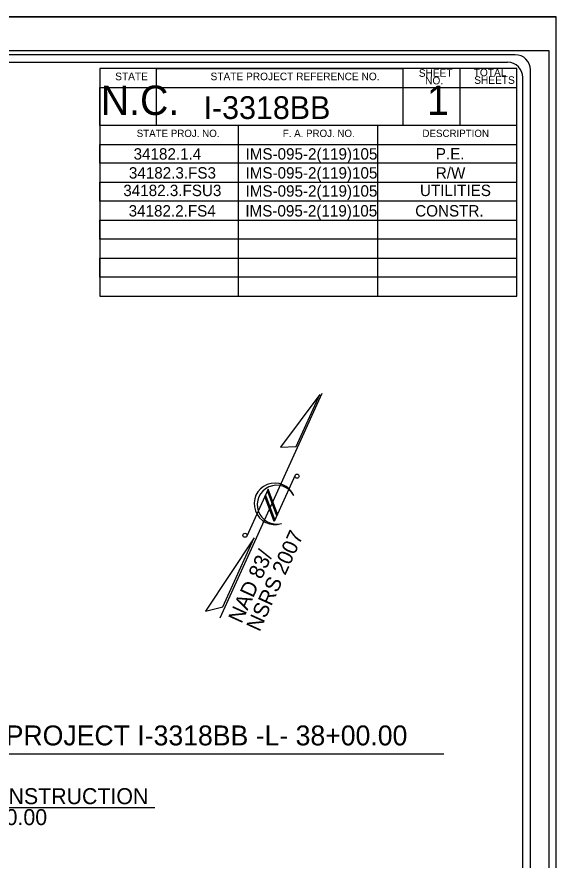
# Model space of a CAD drawing. Extents: x 2241278 to 2254132, y 649924 to 670434.
# Drawn here: x 2251201 to 2252979, y 663621 to 666399 of the extents above; entities that cross this region are included whole.
import ezdxf

# ---------------------------------------------------------------- set-up
doc = ezdxf.new("R2010")
doc.units = 0
for name, color, linetype in [('Prop RDY Alternate Text Yellow', 7, 'Continuous'), ('Sheet Cutting Line CELL', 7, 'Continuous'), ('Sheet Data Field CELL', 7, 'Continuous'), ('Sheet North Arrow CELL', 7, 'Continuous'), ('Sheet Plot Border Inside CELL', 7, 'Continuous'), ('Sheet Plot Border Outside CELL', 7, 'Continuous'), ('Sheet Title CELL', 7, 'Continuous')]:
    doc.layers.add(name, color=color, linetype=linetype)

msp = doc.modelspace()

# ---------------------------------------------------------------- linework, layer by layer
at = {"layer": 'Prop RDY Alternate Text Yellow'}
for p, q in [((2250713.3, 663970.9), (2252608.4, 663970.9)), ((2250873, 663794.9), (2251656.1, 663794.9))]:
    msp.add_line(p, q, dxfattribs=at)
at = {"layer": 'Sheet Cutting Line CELL'}
msp.add_line((2244558.8, 666399.1), (2252978.8, 666399.1), dxfattribs=at)
at = {"layer": 'Sheet North Arrow CELL'}
for p, q in [((2251870.9, 664419.5), (2252207.8, 665158.9)), ((2252118.4, 664888.9), (2252049.3, 664737.1)), ((2252029.3, 664843.1), (2251959, 664688.8)), ((2252060.1, 664760.8), (2252029.3, 664843.1)), ((2252049.3, 664737.1), (2252018.5, 664819.4)), ((2252026.8, 664837.5), (2252020.4, 664823.6)), ((2252051.2, 664741.3), (2252020.4, 664823.6)), ((2252020.4, 664823.6), (2252051.2, 664741.3)), ((2252057.5, 664755.2), (2252026.8, 664837.5)), ((2252113.6, 664822.8), (2252114.1, 664821.9)), ((2252051.2, 664741.3), (2252057.5, 664755.2))]:
    msp.add_line(p, q, dxfattribs=at)
for points in [[(2252199.7, 665154.7), (2252070, 664981.9), (2252122, 664984.1)], [(2251983.6, 664682.7), (2251823, 664441.3), (2251879.9, 664455.2)]]:
    msp.add_lwpolyline(points, close=True, dxfattribs=at)
for centre in [(2252124.4, 664886), (2251952.9, 664691.3)]:
    msp.add_circle(centre, 6.62, dxfattribs=at)
for centre, radius, start, end in [((2252051.4, 664794.8), 68.3, 23.342, 287.896), ((2252057.4, 664792.1), 64, 28.597, 284.1307)]:
    msp.add_arc(centre, radius, start, end, dxfattribs=at)
at = {"layer": 'Sheet Plot Border Inside CELL'}
msp.add_lwpolyline([(2244623.8, 661011.4), (2252956.3, 661011.4), (2252956.3, 666286.9), (2244623.8, 666286.9)], close=True, dxfattribs=at)
at = {"layer": 'Sheet Plot Border Outside CELL'}
msp.add_lwpolyline([(2252978.8, 666399.1), (2244558.8, 666399.1), (2244558.8, 660899.2), (2252978.8, 660899.2)], close=True, dxfattribs=at)
at = {"layer": 'Sheet Title CELL'}
for points in [[(2252843.8, 666274.1), (2245443.7, 666274.2)], [(2252818.8, 666249.1), (2245718.8, 666249.1)], [(2251473.8, 665479.2), (2252848.8, 665479.2), (2252848.8, 665541.6), (2251473.8, 665541.7), (2251473.8, 665604.1), (2252848.8, 665604.1), (2252848.8, 665666.6), (2251473.8, 665666.6), (2251473.8, 665729.2), (2252848.8, 665729.2), (2252848.8, 665791.7), (2251473.8, 665791.7), (2251473.8, 665854.1), (2252848.8, 665854.2), (2252848.8, 665916.6), (2251473.8, 665916.6), (2251473.8, 665979.1), (2252848.8, 665979.1), (2252848.8, 666041.7), (2251473.8, 666041.7), (2251473.8, 666166.7), (2252848.8, 666166.7), (2252848.8, 666229.2), (2251473.8, 666229.1), (2251473.8, 665479.2), (2251932, 665479.1), (2251932, 666041.6), (2251661.3, 666041.6), (2251661.3, 666229.2), (2252473.8, 666229.1), (2252473.8, 666041.7), (2252390.3, 666041.7), (2252390.3, 665479.2), (2252848.8, 665479.2), (2252848.8, 666229.2), (2252661.3, 666229.2), (2252661.3, 666041.7)], [(2252893.8, 661074.2), (2252893.8, 666224.1)], [(2252868.8, 662024.1), (2252868.8, 666199.2)]]:
    msp.add_lwpolyline(points, dxfattribs=at)
for centre in [(2252843.8, 666224.4), (2252818.8, 666199.4)]:
    msp.add_arc(centre, 50, 0, 90, dxfattribs=at)

# ---------------------------------------------------------------- texts
at = {"layer": 'Prop RDY Alternate Text Yellow'}
for s, height, p in [('END TIP PROJECT I-3318BB -L- 38+00.00', 65.626, (2250793.4, 663999.1)), ('END CONSTRUCTION', 52.594, (2250899.8, 663805.5)), ('-L- 38+50.00', 52.594, (2250899.8, 663736.5))]:
    msp.add_text(s, height=height, dxfattribs=at).set_placement(p)
at = {"layer": 'Sheet Data Field CELL'}
for s, height, p in [('I-3318BB  ', 75, (2251816.3, 666062.6)), ('34182.1.4 ', 37.5, (2251585.6, 665928.9)), ('IMS-095-2(119)105', 37.5, (2251954.6, 665928.9)), ('P.E.', 37.5, (2252582, 665929.4)), ('34182.3.FS3', 37.5, (2251570.1, 665866.4)), ('IMS-095-2(119)105', 37.5, (2251954.6, 665866.4)), ('34182.3.FSU3', 37.5, (2251551.8, 665808.6)), ('34182.2.FS4', 37.5, (2251569.3, 665741.4)), ('IMS-095-2(119)105', 37.5, (2251954.1, 665741.4)), ('CONSTR.', 37.5, (2252514.1, 665741.4))]:
    msp.add_text(s, height=height, dxfattribs=at).set_placement(p)
for s, p in [('R/W       ', (2252582, 665866.4)), ('IMS-095-2(119)105', (2251954.6, 665806.8)), ('UTILITIES       ', (2252529.8, 665808.7))]:
    msp.add_text(s, height=37.5, rotation=360, dxfattribs=at).set_placement(p)
at = {"layer": 'Sheet North Arrow CELL'}
for s, p in [('NSRS 2007', (2252000.7, 664371.1)), ('NAD 83/', (2251941.1, 664398.2))]:
    msp.add_text(s, height=50, rotation=65.5019, dxfattribs=at).set_placement(p)
at = {"layer": 'Sheet Title CELL'}
for s, height, p in [('TOTAL', 25, (2252707, 666203.4)), ('STATE', 25, (2251525, 666190.4)), ('STATE PROJECT REFERENCE NO.', 24.999, (2251839.3, 666190.4)), ('SHEET', 25, (2252526, 666201.6)), ('NO.', 25, (2252546.8, 666176.9)), ('SHEETS', 25, (2252708.7, 666178.4)), ('N.C.', 96.75, (2251477.5, 666075.9)), ('1', 96.7, (2252553, 666075.9)), ('STATE PROJ. NO.', 24, (2251596, 666003.4)), ('F. A. PROJ. NO.', 24, (2252077.5, 666003.4)), ('DESCRIPTION', 24, (2252538, 666003.4))]:
    msp.add_text(s, height=height, rotation=360, dxfattribs=at).set_placement(p)

doc.saveas('drawing.dxf')
